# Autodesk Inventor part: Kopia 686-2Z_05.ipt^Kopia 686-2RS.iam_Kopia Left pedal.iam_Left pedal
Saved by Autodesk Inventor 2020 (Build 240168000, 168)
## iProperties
Created: 2017-10
Part Number: Kopia 686-2Z_05.ipt^Kopia 686-2RS.iam_Kopia Left pedal.iam_Left pedal
Material: Ogólny
Document SubType Name: Modeling
Designer: Tomasz
Density: 1 g/cm^3
Appearance: Domyślna
Sending System: SolidWorks 2017
Last Author: Tomasz
Last Saved: 2017-10-01
Author: Tomasz
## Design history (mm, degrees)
